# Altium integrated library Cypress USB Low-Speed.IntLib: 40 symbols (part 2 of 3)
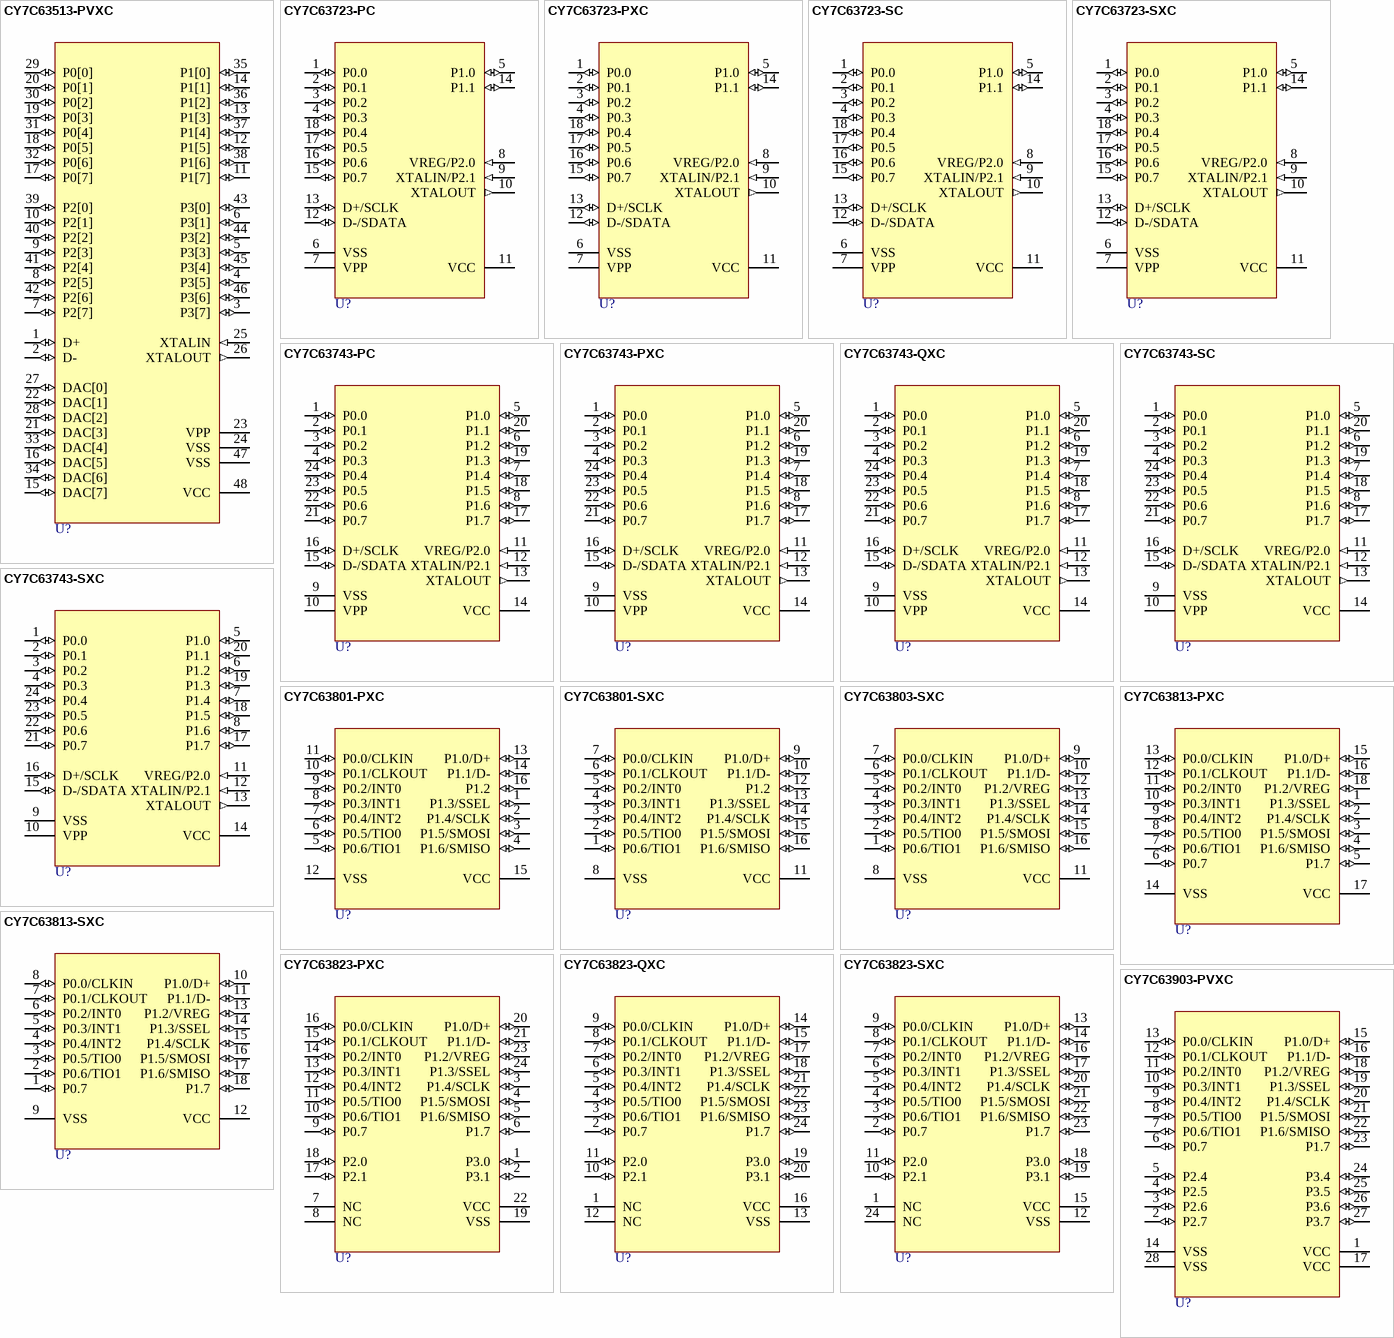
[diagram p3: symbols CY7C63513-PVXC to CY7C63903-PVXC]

## CY7C63723-PC
designator U?
enCoRe, Low-Speed Combination USB and PS/2 Peripheral Controller, 8KB EPROM, 18-Pin PDIP, Commercial Grade
footprint P3 (DIP, 18-Leads, Row Spacing 7.62mm, Pitch 2.54mm, Body 22.73x6.48mm)
pins: 1 P0.0 (io) "GPIO Port 0 capable of sinking up to 50 mA/pin, or sinking controlled low or high programmable current. Can also source 2 mA current, provide a resistive pull-up, or serve as a high-impedance input. Provides input to Capture Timer A.", 2 P0.1 (io) "GPIO Port 0 capable of sinking up to 50 mA/pin, or sinking controlled low or high programmable current. Can also source 2 mA current, provide a resistive pull-up, or serve as a high-impedance input. Provides input to Capture Timer B.", 3 P0.2 (io) "GPIO Port 0 capable of sinking up to 50 mA/pin, or sinking controlled low or high programmable current. Can also source 2 mA current, provide a resistive pull-up, or serve as a high-impedance input.", 4 P0.3 (io) "GPIO Port 0 capable of sinking up to 50 mA/pin, or sinking controlled low or high programmable current. Can also source 2 mA current, provide a resistive pull-up, or serve as a high-impedance input.", 5 P1.0 (io) "IO Port 1 capable of sinking up to 50 mA/pin, or sinking controlled low or high programmable current. Can also source 2 mA current, provide a resistive pull-up, or serve as a high-impedance input.", 6 VSS (power) "Ground", 7 VPP (power) "Programming voltage supply, ground for normal operation", 8 VREG/P2.0 (in) "Voltage supply for 1.3-kOhm USB pull-up resistor (3.3V nominal). Also serves as P2.0 input.", 9 XTALIN/P2.1 (in) "6-MHz ceramic resonator or external clock input, or P2.1 input", 10 XTALOUT (out) "6-MHz ceramic resonator return pin or internal oscillator output", 11 VCC (power) "Voltage supply", 12 D-/SDATA (io) "USB differential data line or PS/2 data signal", 13 D+/SCLK (io) "USB differential data line or PS/2 clock signal", 14 P1.1 (io) "IO Port 1 capable of sinking up to 50 mA/pin, or sinking controlled low or high programmable current. Can also source 2 mA current, provide a resistive pull-up, or serve as a high-impedance input.", 15 P0.7 (io) "GPIO Port 0 capable of sinking up to 50 mA/pin, or sinking controlled low or high programmable current. Can also source 2 mA current, provide a resistive pull-up, or serve as a high-impedance input.", 16 P0.6 (io) "GPIO Port 0 capable of sinking up to 50 mA/pin, or sinking controlled low or high programmable current. Can also source 2 mA current, provide a resistive pull-up, or serve as a high-impedance input.", 17 P0.5 (io) "GPIO Port 0 capable of sinking up to 50 mA/pin, or sinking controlled low or high programmable current. Can also source 2 mA current, provide a resistive pull-up, or serve as a high-impedance input.", 18 P0.4 (io) "GPIO Port 0 capable of sinking up to 50 mA/pin, or sinking controlled low or high programmable current. Can also source 2 mA current, provide a resistive pull-up, or serve as a high-impedance input."

## CY7C63723-PXC
designator U?
enCoRe, Low-Speed Combination USB and PS/2 Peripheral Controller, 8KB EPROM, 18-Pin PDIP, Commercial Grade, Pb-free
footprint P3 (DIP, 18-Leads, Row Spacing 7.62mm, Pitch 2.54mm, Body 22.73x6.48mm)
pins: 1 P0.0 (io) "GPIO Port 0 capable of sinking up to 50 mA/pin, or sinking controlled low or high programmable current. Can also source 2 mA current, provide a resistive pull-up, or serve as a high-impedance input. Provides input to Capture Timer A.", 2 P0.1 (io) "GPIO Port 0 capable of sinking up to 50 mA/pin, or sinking controlled low or high programmable current. Can also source 2 mA current, provide a resistive pull-up, or serve as a high-impedance input. Provides input to Capture Timer B.", 3 P0.2 (io) "GPIO Port 0 capable of sinking up to 50 mA/pin, or sinking controlled low or high programmable current. Can also source 2 mA current, provide a resistive pull-up, or serve as a high-impedance input.", 4 P0.3 (io) "GPIO Port 0 capable of sinking up to 50 mA/pin, or sinking controlled low or high programmable current. Can also source 2 mA current, provide a resistive pull-up, or serve as a high-impedance input.", 5 P1.0 (io) "IO Port 1 capable of sinking up to 50 mA/pin, or sinking controlled low or high programmable current. Can also source 2 mA current, provide a resistive pull-up, or serve as a high-impedance input.", 6 VSS (power) "Ground", 7 VPP (power) "Programming voltage supply, ground for normal operation", 8 VREG/P2.0 (in) "Voltage supply for 1.3-kOhm USB pull-up resistor (3.3V nominal). Also serves as P2.0 input.", 9 XTALIN/P2.1 (in) "6-MHz ceramic resonator or external clock input, or P2.1 input", 10 XTALOUT (out) "6-MHz ceramic resonator return pin or internal oscillator output", 11 VCC (power) "Voltage supply", 12 D-/SDATA (io) "USB differential data line or PS/2 data signal", 13 D+/SCLK (io) "USB differential data line or PS/2 clock signal", 14 P1.1 (io) "IO Port 1 capable of sinking up to 50 mA/pin, or sinking controlled low or high programmable current. Can also source 2 mA current, provide a resistive pull-up, or serve as a high-impedance input.", 15 P0.7 (io) "GPIO Port 0 capable of sinking up to 50 mA/pin, or sinking controlled low or high programmable current. Can also source 2 mA current, provide a resistive pull-up, or serve as a high-impedance input.", 16 P0.6 (io) "GPIO Port 0 capable of sinking up to 50 mA/pin, or sinking controlled low or high programmable current. Can also source 2 mA current, provide a resistive pull-up, or serve as a high-impedance input.", 17 P0.5 (io) "GPIO Port 0 capable of sinking up to 50 mA/pin, or sinking controlled low or high programmable current. Can also source 2 mA current, provide a resistive pull-up, or serve as a high-impedance input.", 18 P0.4 (io) "GPIO Port 0 capable of sinking up to 50 mA/pin, or sinking controlled low or high programmable current. Can also source 2 mA current, provide a resistive pull-up, or serve as a high-impedance input."

## CY7C63723-SC
designator U?
enCoRe, Low-Speed Combination USB and PS/2 Peripheral Controller, 8KB EPROM, 18-Pin SOIC, Commercial Grade
footprint S3_N (SOIC, 18-Leads, Body 11.6x7.5mm, Pitch 1.27mm, IPC Medium Density)
footprint S3_L (SOIC, 18-Leads, Body 11.6x7.5mm, Pitch 1.27mm, IPC High Density)
footprint S3_M (SOIC, 18-Leads, Body 11.6x7.5mm, Pitch 1.27mm, IPC Low Density)
pins: 1 P0.0 (io) "GPIO Port 0 capable of sinking up to 50 mA/pin, or sinking controlled low or high programmable current. Can also source 2 mA current, provide a resistive pull-up, or serve as a high-impedance input. Provides input to Capture Timer A.", 2 P0.1 (io) "GPIO Port 0 capable of sinking up to 50 mA/pin, or sinking controlled low or high programmable current. Can also source 2 mA current, provide a resistive pull-up, or serve as a high-impedance input. Provides input to Capture Timer B.", 3 P0.2 (io) "GPIO Port 0 capable of sinking up to 50 mA/pin, or sinking controlled low or high programmable current. Can also source 2 mA current, provide a resistive pull-up, or serve as a high-impedance input.", 4 P0.3 (io) "GPIO Port 0 capable of sinking up to 50 mA/pin, or sinking controlled low or high programmable current. Can also source 2 mA current, provide a resistive pull-up, or serve as a high-impedance input.", 5 P1.0 (io) "IO Port 1 capable of sinking up to 50 mA/pin, or sinking controlled low or high programmable current. Can also source 2 mA current, provide a resistive pull-up, or serve as a high-impedance input.", 6 VSS (power) "Ground", 7 VPP (power) "Programming voltage supply, ground for normal operation", 8 VREG/P2.0 (in) "Voltage supply for 1.3-kOhm USB pull-up resistor (3.3V nominal). Also serves as P2.0 input.", 9 XTALIN/P2.1 (in) "6-MHz ceramic resonator or external clock input, or P2.1 input", 10 XTALOUT (out) "6-MHz ceramic resonator return pin or internal oscillator output", 11 VCC (power) "Voltage supply", 12 D-/SDATA (io) "USB differential data line or PS/2 data signal", 13 D+/SCLK (io) "USB differential data line or PS/2 clock signal", 14 P1.1 (io) "IO Port 1 capable of sinking up to 50 mA/pin, or sinking controlled low or high programmable current. Can also source 2 mA current, provide a resistive pull-up, or serve as a high-impedance input.", 15 P0.7 (io) "GPIO Port 0 capable of sinking up to 50 mA/pin, or sinking controlled low or high programmable current. Can also source 2 mA current, provide a resistive pull-up, or serve as a high-impedance input.", 16 P0.6 (io) "GPIO Port 0 capable of sinking up to 50 mA/pin, or sinking controlled low or high programmable current. Can also source 2 mA current, provide a resistive pull-up, or serve as a high-impedance input.", 17 P0.5 (io) "GPIO Port 0 capable of sinking up to 50 mA/pin, or sinking controlled low or high programmable current. Can also source 2 mA current, provide a resistive pull-up, or serve as a high-impedance input.", 18 P0.4 (io) "GPIO Port 0 capable of sinking up to 50 mA/pin, or sinking controlled low or high programmable current. Can also source 2 mA current, provide a resistive pull-up, or serve as a high-impedance input."

## CY7C63723-SXC
designator U?
enCoRe, Low-Speed Combination USB and PS/2 Peripheral Controller, 8KB EPROM, 18-Pin SOIC, Commercial Grade, Pb-free
footprint S3_N (SOIC, 18-Leads, Body 11.6x7.5mm, Pitch 1.27mm, IPC Medium Density)
footprint S3_L (SOIC, 18-Leads, Body 11.6x7.5mm, Pitch 1.27mm, IPC High Density)
footprint S3_M (SOIC, 18-Leads, Body 11.6x7.5mm, Pitch 1.27mm, IPC Low Density)
pins: 1 P0.0 (io) "GPIO Port 0 capable of sinking up to 50 mA/pin, or sinking controlled low or high programmable current. Can also source 2 mA current, provide a resistive pull-up, or serve as a high-impedance input. Provides input to Capture Timer A.", 2 P0.1 (io) "GPIO Port 0 capable of sinking up to 50 mA/pin, or sinking controlled low or high programmable current. Can also source 2 mA current, provide a resistive pull-up, or serve as a high-impedance input. Provides input to Capture Timer B.", 3 P0.2 (io) "GPIO Port 0 capable of sinking up to 50 mA/pin, or sinking controlled low or high programmable current. Can also source 2 mA current, provide a resistive pull-up, or serve as a high-impedance input.", 4 P0.3 (io) "GPIO Port 0 capable of sinking up to 50 mA/pin, or sinking controlled low or high programmable current. Can also source 2 mA current, provide a resistive pull-up, or serve as a high-impedance input.", 5 P1.0 (io) "IO Port 1 capable of sinking up to 50 mA/pin, or sinking controlled low or high programmable current. Can also source 2 mA current, provide a resistive pull-up, or serve as a high-impedance input.", 6 VSS (power) "Ground", 7 VPP (power) "Programming voltage supply, ground for normal operation", 8 VREG/P2.0 (in) "Voltage supply for 1.3-kOhm USB pull-up resistor (3.3V nominal). Also serves as P2.0 input.", 9 XTALIN/P2.1 (in) "6-MHz ceramic resonator or external clock input, or P2.1 input", 10 XTALOUT (out) "6-MHz ceramic resonator return pin or internal oscillator output", 11 VCC (power) "Voltage supply", 12 D-/SDATA (io) "USB differential data line or PS/2 data signal", 13 D+/SCLK (io) "USB differential data line or PS/2 clock signal", 14 P1.1 (io) "IO Port 1 capable of sinking up to 50 mA/pin, or sinking controlled low or high programmable current. Can also source 2 mA current, provide a resistive pull-up, or serve as a high-impedance input.", 15 P0.7 (io) "GPIO Port 0 capable of sinking up to 50 mA/pin, or sinking controlled low or high programmable current. Can also source 2 mA current, provide a resistive pull-up, or serve as a high-impedance input.", 16 P0.6 (io) "GPIO Port 0 capable of sinking up to 50 mA/pin, or sinking controlled low or high programmable current. Can also source 2 mA current, provide a resistive pull-up, or serve as a high-impedance input.", 17 P0.5 (io) "GPIO Port 0 capable of sinking up to 50 mA/pin, or sinking controlled low or high programmable current. Can also source 2 mA current, provide a resistive pull-up, or serve as a high-impedance input.", 18 P0.4 (io) "GPIO Port 0 capable of sinking up to 50 mA/pin, or sinking controlled low or high programmable current. Can also source 2 mA current, provide a resistive pull-up, or serve as a high-impedance input."

## CY7C63743-PC
designator U?
enCoRe, Low-Speed Combination USB and PS/2 Peripheral Controller, 8KB EPROM, 24-Pin PDIP, Commercial Grade
footprint P13 (DIP, 24-Leads, Row Spacing 7.62mm, Pitch 2.54mm, Body 31.75x6.6mm)
pins: 1 P0.0 (io) "GPIO Port 0 capable of sinking up to 50 mA/pin, or sinking controlled low or high programmable current. Can also source 2 mA current, provide a resistive pull-up, or serve as a high-impedance input. Provides input to Capture Timer A.", 2 P0.1 (io) "GPIO Port 0 capable of sinking up to 50 mA/pin, or sinking controlled low or high programmable current. Can also source 2 mA current, provide a resistive pull-up, or serve as a high-impedance input. Provides input to Capture Timer B.", 3 P0.2 (io) "GPIO Port 0 capable of sinking up to 50 mA/pin, or sinking controlled low or high programmable current. Can also source 2 mA current, provide a resistive pull-up, or serve as a high-impedance input.", 4 P0.3 (io) "GPIO Port 0 capable of sinking up to 50 mA/pin, or sinking controlled low or high programmable current. Can also source 2 mA current, provide a resistive pull-up, or serve as a high-impedance input.", 5 P1.0 (io) "IO Port 1 capable of sinking up to 50 mA/pin, or sinking controlled low or high programmable current. Can also source 2 mA current, provide a resistive pull-up, or serve as a high-impedance input.", 6 P1.2 (io) "IO Port 1 capable of sinking up to 50 mA/pin, or sinking controlled low or high programmable current. Can also source 2 mA current, provide a resistive pull-up, or serve as a high-impedance input.", 7 P1.4 (io) "IO Port 1 capable of sinking up to 50 mA/pin, or sinking controlled low or high programmable current. Can also source 2 mA current, provide a resistive pull-up, or serve as a high-impedance input.", 8 P1.6 (io) "IO Port 1 capable of sinking up to 50 mA/pin, or sinking controlled low or high programmable current. Can also source 2 mA current, provide a resistive pull-up, or serve as a high-impedance input.", 9 VSS (power) "Ground", 10 VPP (power) "Programming voltage supply, ground for normal operation", 11 VREG/P2.0 (in) "Voltage supply for 1.3-kOhm USB pull-up resistor (3.3V nominal). Also serves as P2.0 input.", 12 XTALIN/P2.1 (in) "6-MHz ceramic resonator or external clock input, or P2.1 input", 13 XTALOUT (out) "6-MHz ceramic resonator return pin or internal oscillator output", 14 VCC (power) "Voltage supply", 15 D-/SDATA (io) "USB differential data line or PS/2 data signal", 16 D+/SCLK (io) "USB differential data line or PS/2 clock signal", 17 P1.7 (io) "IO Port 1 capable of sinking up to 50 mA/pin, or sinking controlled low or high programmable current. Can also source 2 mA current, provide a resistive pull-up, or serve as a high-impedance input.", 18 P1.5 (io) "IO Port 1 capable of sinking up to 50 mA/pin, or sinking controlled low or high programmable current. Can also source 2 mA current, provide a resistive pull-up, or serve as a high-impedance input.", 19 P1.3 (io) "IO Port 1 capable of sinking up to 50 mA/pin, or sinking controlled low or high programmable current. Can also source 2 mA current, provide a resistive pull-up, or serve as a high-impedance input.", 20 P1.1 (io) "IO Port 1 capable of sinking up to 50 mA/pin, or sinking controlled low or high programmable current. Can also source 2 mA current, provide a resistive pull-up, or serve as a high-impedance input.", 21 P0.7 (io) "GPIO Port 0 capable of sinking up to 50 mA/pin, or sinking controlled low or high programmable current. Can also source 2 mA current, provide a resistive pull-up, or serve as a high-impedance input.", 22 P0.6 (io) "GPIO Port 0 capable of sinking up to 50 mA/pin, or sinking controlled low or high programmable current. Can also source 2 mA current, provide a resistive pull-up, or serve as a high-impedance input.", 23 P0.5 (io) "GPIO Port 0 capable of sinking up to 50 mA/pin, or sinking controlled low or high programmable current. Can also source 2 mA current, provide a resistive pull-up, or serve as a high-impedance input.", 24 P0.4 (io) "GPIO Port 0 capable of sinking up to 50 mA/pin, or sinking controlled low or high programmable current. Can also source 2 mA current, provide a resistive pull-up, or serve as a high-impedance input."

## CY7C63743-PXC
designator U?
enCoRe, Low-Speed Combination USB and PS/2 Peripheral Controller, 8KB EPROM, 24-Pin PDIP, Commercial Grade, Pb-free
footprint P13 (DIP, 24-Leads, Row Spacing 7.62mm, Pitch 2.54mm, Body 31.75x6.6mm)
pins: 1 P0.0 (io) "GPIO Port 0 capable of sinking up to 50 mA/pin, or sinking controlled low or high programmable current. Can also source 2 mA current, provide a resistive pull-up, or serve as a high-impedance input. Provides input to Capture Timer A.", 2 P0.1 (io) "GPIO Port 0 capable of sinking up to 50 mA/pin, or sinking controlled low or high programmable current. Can also source 2 mA current, provide a resistive pull-up, or serve as a high-impedance input. Provides input to Capture Timer B.", 3 P0.2 (io) "GPIO Port 0 capable of sinking up to 50 mA/pin, or sinking controlled low or high programmable current. Can also source 2 mA current, provide a resistive pull-up, or serve as a high-impedance input.", 4 P0.3 (io) "GPIO Port 0 capable of sinking up to 50 mA/pin, or sinking controlled low or high programmable current. Can also source 2 mA current, provide a resistive pull-up, or serve as a high-impedance input.", 5 P1.0 (io) "IO Port 1 capable of sinking up to 50 mA/pin, or sinking controlled low or high programmable current. Can also source 2 mA current, provide a resistive pull-up, or serve as a high-impedance input.", 6 P1.2 (io) "IO Port 1 capable of sinking up to 50 mA/pin, or sinking controlled low or high programmable current. Can also source 2 mA current, provide a resistive pull-up, or serve as a high-impedance input.", 7 P1.4 (io) "IO Port 1 capable of sinking up to 50 mA/pin, or sinking controlled low or high programmable current. Can also source 2 mA current, provide a resistive pull-up, or serve as a high-impedance input.", 8 P1.6 (io) "IO Port 1 capable of sinking up to 50 mA/pin, or sinking controlled low or high programmable current. Can also source 2 mA current, provide a resistive pull-up, or serve as a high-impedance input.", 9 VSS (power) "Ground", 10 VPP (power) "Programming voltage supply, ground for normal operation", 11 VREG/P2.0 (in) "Voltage supply for 1.3-kOhm USB pull-up resistor (3.3V nominal). Also serves as P2.0 input.", 12 XTALIN/P2.1 (in) "6-MHz ceramic resonator or external clock input, or P2.1 input", 13 XTALOUT (out) "6-MHz ceramic resonator return pin or internal oscillator output", 14 VCC (power) "Voltage supply", 15 D-/SDATA (io) "USB differential data line or PS/2 data signal", 16 D+/SCLK (io) "USB differential data line or PS/2 clock signal", 17 P1.7 (io) "IO Port 1 capable of sinking up to 50 mA/pin, or sinking controlled low or high programmable current. Can also source 2 mA current, provide a resistive pull-up, or serve as a high-impedance input.", 18 P1.5 (io) "IO Port 1 capable of sinking up to 50 mA/pin, or sinking controlled low or high programmable current. Can also source 2 mA current, provide a resistive pull-up, or serve as a high-impedance input.", 19 P1.3 (io) "IO Port 1 capable of sinking up to 50 mA/pin, or sinking controlled low or high programmable current. Can also source 2 mA current, provide a resistive pull-up, or serve as a high-impedance input.", 20 P1.1 (io) "IO Port 1 capable of sinking up to 50 mA/pin, or sinking controlled low or high programmable current. Can also source 2 mA current, provide a resistive pull-up, or serve as a high-impedance input.", 21 P0.7 (io) "GPIO Port 0 capable of sinking up to 50 mA/pin, or sinking controlled low or high programmable current. Can also source 2 mA current, provide a resistive pull-up, or serve as a high-impedance input.", 22 P0.6 (io) "GPIO Port 0 capable of sinking up to 50 mA/pin, or sinking controlled low or high programmable current. Can also source 2 mA current, provide a resistive pull-up, or serve as a high-impedance input.", 23 P0.5 (io) "GPIO Port 0 capable of sinking up to 50 mA/pin, or sinking controlled low or high programmable current. Can also source 2 mA current, provide a resistive pull-up, or serve as a high-impedance input.", 24 P0.4 (io) "GPIO Port 0 capable of sinking up to 50 mA/pin, or sinking controlled low or high programmable current. Can also source 2 mA current, provide a resistive pull-up, or serve as a high-impedance input."

## CY7C63743-QXC
designator U?
enCoRe, Low-Speed Combination USB and PS/2 Peripheral Controller, 8KB EPROM, 24-Pin QSOP, Commercial Grade, Pb-free
footprint Q13_N (SOP, 24-Leads, Body 8.6x3.9mm, Pitch 0.635mm, IPC Medium Density)
footprint Q13_L (SOP, 24-Leads, Body 8.6x3.9mm, Pitch 0.635mm, IPC High Density)
footprint Q13_M (SOP, 24-Leads, Body 8.6x3.9mm, Pitch 0.635mm, IPC Low Density)
pins: 1 P0.0 (io) "GPIO Port 0 capable of sinking up to 50 mA/pin, or sinking controlled low or high programmable current. Can also source 2 mA current, provide a resistive pull-up, or serve as a high-impedance input. Provides input to Capture Timer A.", 2 P0.1 (io) "GPIO Port 0 capable of sinking up to 50 mA/pin, or sinking controlled low or high programmable current. Can also source 2 mA current, provide a resistive pull-up, or serve as a high-impedance input. Provides input to Capture Timer B.", 3 P0.2 (io) "GPIO Port 0 capable of sinking up to 50 mA/pin, or sinking controlled low or high programmable current. Can also source 2 mA current, provide a resistive pull-up, or serve as a high-impedance input.", 4 P0.3 (io) "GPIO Port 0 capable of sinking up to 50 mA/pin, or sinking controlled low or high programmable current. Can also source 2 mA current, provide a resistive pull-up, or serve as a high-impedance input.", 5 P1.0 (io) "IO Port 1 capable of sinking up to 50 mA/pin, or sinking controlled low or high programmable current. Can also source 2 mA current, provide a resistive pull-up, or serve as a high-impedance input.", 6 P1.2 (io) "IO Port 1 capable of sinking up to 50 mA/pin, or sinking controlled low or high programmable current. Can also source 2 mA current, provide a resistive pull-up, or serve as a high-impedance input.", 7 P1.4 (io) "IO Port 1 capable of sinking up to 50 mA/pin, or sinking controlled low or high programmable current. Can also source 2 mA current, provide a resistive pull-up, or serve as a high-impedance input.", 8 P1.6 (io) "IO Port 1 capable of sinking up to 50 mA/pin, or sinking controlled low or high programmable current. Can also source 2 mA current, provide a resistive pull-up, or serve as a high-impedance input.", 9 VSS (power) "Ground", 10 VPP (power) "Programming voltage supply, ground for normal operation", 11 VREG/P2.0 (in) "Voltage supply for 1.3-kOhm USB pull-up resistor (3.3V nominal). Also serves as P2.0 input.", 12 XTALIN/P2.1 (in) "6-MHz ceramic resonator or external clock input, or P2.1 input", 13 XTALOUT (out) "6-MHz ceramic resonator return pin or internal oscillator output", 14 VCC (power) "Voltage supply", 15 D-/SDATA (io) "USB differential data line or PS/2 data signal", 16 D+/SCLK (io) "USB differential data line or PS/2 clock signal", 17 P1.7 (io) "IO Port 1 capable of sinking up to 50 mA/pin, or sinking controlled low or high programmable current. Can also source 2 mA current, provide a resistive pull-up, or serve as a high-impedance input.", 18 P1.5 (io) "IO Port 1 capable of sinking up to 50 mA/pin, or sinking controlled low or high programmable current. Can also source 2 mA current, provide a resistive pull-up, or serve as a high-impedance input.", 19 P1.3 (io) "IO Port 1 capable of sinking up to 50 mA/pin, or sinking controlled low or high programmable current. Can also source 2 mA current, provide a resistive pull-up, or serve as a high-impedance input.", 20 P1.1 (io) "IO Port 1 capable of sinking up to 50 mA/pin, or sinking controlled low or high programmable current. Can also source 2 mA current, provide a resistive pull-up, or serve as a high-impedance input.", 21 P0.7 (io) "GPIO Port 0 capable of sinking up to 50 mA/pin, or sinking controlled low or high programmable current. Can also source 2 mA current, provide a resistive pull-up, or serve as a high-impedance input.", 22 P0.6 (io) "GPIO Port 0 capable of sinking up to 50 mA/pin, or sinking controlled low or high programmable current. Can also source 2 mA current, provide a resistive pull-up, or serve as a high-impedance input.", 23 P0.5 (io) "GPIO Port 0 capable of sinking up to 50 mA/pin, or sinking controlled low or high programmable current. Can also source 2 mA current, provide a resistive pull-up, or serve as a high-impedance input.", 24 P0.4 (io) "GPIO Port 0 capable of sinking up to 50 mA/pin, or sinking controlled low or high programmable current. Can also source 2 mA current, provide a resistive pull-up, or serve as a high-impedance input."

## CY7C63743-SC
designator U?
enCoRe, Low-Speed Combination USB and PS/2 Peripheral Controller, 8KB EPROM, 24-Pin SOIC,Commercial Grade
footprint S13_N (SOIC, 24-Leads, Body 15.4x7.5mm, Pitch 1.27mm, IPC Medium Density)
footprint S13_L (SOIC, 24-Leads, Body 15.4x7.5mm, Pitch 1.27mm, IPC High Density)
footprint S13_M (SOIC, 24-Leads, Body 15.4x7.5mm, Pitch 1.27mm, IPC Low Density)
pins: 1 P0.0 (io) "GPIO Port 0 capable of sinking up to 50 mA/pin, or sinking controlled low or high programmable current. Can also source 2 mA current, provide a resistive pull-up, or serve as a high-impedance input. Provides input to Capture Timer A.", 2 P0.1 (io) "GPIO Port 0 capable of sinking up to 50 mA/pin, or sinking controlled low or high programmable current. Can also source 2 mA current, provide a resistive pull-up, or serve as a high-impedance input. Provides input to Capture Timer B.", 3 P0.2 (io) "GPIO Port 0 capable of sinking up to 50 mA/pin, or sinking controlled low or high programmable current. Can also source 2 mA current, provide a resistive pull-up, or serve as a high-impedance input.", 4 P0.3 (io) "GPIO Port 0 capable of sinking up to 50 mA/pin, or sinking controlled low or high programmable current. Can also source 2 mA current, provide a resistive pull-up, or serve as a high-impedance input.", 5 P1.0 (io) "IO Port 1 capable of sinking up to 50 mA/pin, or sinking controlled low or high programmable current. Can also source 2 mA current, provide a resistive pull-up, or serve as a high-impedance input.", 6 P1.2 (io) "IO Port 1 capable of sinking up to 50 mA/pin, or sinking controlled low or high programmable current. Can also source 2 mA current, provide a resistive pull-up, or serve as a high-impedance input.", 7 P1.4 (io) "IO Port 1 capable of sinking up to 50 mA/pin, or sinking controlled low or high programmable current. Can also source 2 mA current, provide a resistive pull-up, or serve as a high-impedance input.", 8 P1.6 (io) "IO Port 1 capable of sinking up to 50 mA/pin, or sinking controlled low or high programmable current. Can also source 2 mA current, provide a resistive pull-up, or serve as a high-impedance input.", 9 VSS (power) "Ground", 10 VPP (power) "Programming voltage supply, ground for normal operation", 11 VREG/P2.0 (in) "Voltage supply for 1.3-kOhm USB pull-up resistor (3.3V nominal). Also serves as P2.0 input.", 12 XTALIN/P2.1 (in) "6-MHz ceramic resonator or external clock input, or P2.1 input", 13 XTALOUT (out) "6-MHz ceramic resonator return pin or internal oscillator output", 14 VCC (power) "Voltage supply", 15 D-/SDATA (io) "USB differential data line or PS/2 data signal", 16 D+/SCLK (io) "USB differential data line or PS/2 clock signal", 17 P1.7 (io) "IO Port 1 capable of sinking up to 50 mA/pin, or sinking controlled low or high programmable current. Can also source 2 mA current, provide a resistive pull-up, or serve as a high-impedance input.", 18 P1.5 (io) "IO Port 1 capable of sinking up to 50 mA/pin, or sinking controlled low or high programmable current. Can also source 2 mA current, provide a resistive pull-up, or serve as a high-impedance input.", 19 P1.3 (io) "IO Port 1 capable of sinking up to 50 mA/pin, or sinking controlled low or high programmable current. Can also source 2 mA current, provide a resistive pull-up, or serve as a high-impedance input.", 20 P1.1 (io) "IO Port 1 capable of sinking up to 50 mA/pin, or sinking controlled low or high programmable current. Can also source 2 mA current, provide a resistive pull-up, or serve as a high-impedance input.", 21 P0.7 (io) "GPIO Port 0 capable of sinking up to 50 mA/pin, or sinking controlled low or high programmable current. Can also source 2 mA current, provide a resistive pull-up, or serve as a high-impedance input.", 22 P0.6 (io) "GPIO Port 0 capable of sinking up to 50 mA/pin, or sinking controlled low or high programmable current. Can also source 2 mA current, provide a resistive pull-up, or serve as a high-impedance input.", 23 P0.5 (io) "GPIO Port 0 capable of sinking up to 50 mA/pin, or sinking controlled low or high programmable current. Can also source 2 mA current, provide a resistive pull-up, or serve as a high-impedance input.", 24 P0.4 (io) "GPIO Port 0 capable of sinking up to 50 mA/pin, or sinking controlled low or high programmable current. Can also source 2 mA current, provide a resistive pull-up, or serve as a high-impedance input."

## CY7C63743-SXC
designator U?
enCoRe, Low-Speed Combination USB and PS/2 Peripheral Controller, 8KB EPROM, 24-Pin SOIC,Commercial Grade, Pb-free
footprint S13_N (SOIC, 24-Leads, Body 15.4x7.5mm, Pitch 1.27mm, IPC Medium Density)
footprint S13_L (SOIC, 24-Leads, Body 15.4x7.5mm, Pitch 1.27mm, IPC High Density)
footprint S13_M (SOIC, 24-Leads, Body 15.4x7.5mm, Pitch 1.27mm, IPC Low Density)
pins: 1 P0.0 (io) "GPIO Port 0 capable of sinking up to 50 mA/pin, or sinking controlled low or high programmable current. Can also source 2 mA current, provide a resistive pull-up, or serve as a high-impedance input. Provides input to Capture Timer A.", 2 P0.1 (io) "GPIO Port 0 capable of sinking up to 50 mA/pin, or sinking controlled low or high programmable current. Can also source 2 mA current, provide a resistive pull-up, or serve as a high-impedance input. Provides input to Capture Timer B.", 3 P0.2 (io) "GPIO Port 0 capable of sinking up to 50 mA/pin, or sinking controlled low or high programmable current. Can also source 2 mA current, provide a resistive pull-up, or serve as a high-impedance input.", 4 P0.3 (io) "GPIO Port 0 capable of sinking up to 50 mA/pin, or sinking controlled low or high programmable current. Can also source 2 mA current, provide a resistive pull-up, or serve as a high-impedance input.", 5 P1.0 (io) "IO Port 1 capable of sinking up to 50 mA/pin, or sinking controlled low or high programmable current. Can also source 2 mA current, provide a resistive pull-up, or serve as a high-impedance input.", 6 P1.2 (io) "IO Port 1 capable of sinking up to 50 mA/pin, or sinking controlled low or high programmable current. Can also source 2 mA current, provide a resistive pull-up, or serve as a high-impedance input.", 7 P1.4 (io) "IO Port 1 capable of sinking up to 50 mA/pin, or sinking controlled low or high programmable current. Can also source 2 mA current, provide a resistive pull-up, or serve as a high-impedance input.", 8 P1.6 (io) "IO Port 1 capable of sinking up to 50 mA/pin, or sinking controlled low or high programmable current. Can also source 2 mA current, provide a resistive pull-up, or serve as a high-impedance input.", 9 VSS (power) "Ground", 10 VPP (power) "Programming voltage supply, ground for normal operation", 11 VREG/P2.0 (in) "Voltage supply for 1.3-kOhm USB pull-up resistor (3.3V nominal). Also serves as P2.0 input.", 12 XTALIN/P2.1 (in) "6-MHz ceramic resonator or external clock input, or P2.1 input", 13 XTALOUT (out) "6-MHz ceramic resonator return pin or internal oscillator output", 14 VCC (power) "Voltage supply", 15 D-/SDATA (io) "USB differential data line or PS/2 data signal", 16 D+/SCLK (io) "USB differential data line or PS/2 clock signal", 17 P1.7 (io) "IO Port 1 capable of sinking up to 50 mA/pin, or sinking controlled low or high programmable current. Can also source 2 mA current, provide a resistive pull-up, or serve as a high-impedance input.", 18 P1.5 (io) "IO Port 1 capable of sinking up to 50 mA/pin, or sinking controlled low or high programmable current. Can also source 2 mA current, provide a resistive pull-up, or serve as a high-impedance input.", 19 P1.3 (io) "IO Port 1 capable of sinking up to 50 mA/pin, or sinking controlled low or high programmable current. Can also source 2 mA current, provide a resistive pull-up, or serve as a high-impedance input.", 20 P1.1 (io) "IO Port 1 capable of sinking up to 50 mA/pin, or sinking controlled low or high programmable current. Can also source 2 mA current, provide a resistive pull-up, or serve as a high-impedance input.", 21 P0.7 (io) "GPIO Port 0 capable of sinking up to 50 mA/pin, or sinking controlled low or high programmable current. Can also source 2 mA current, provide a resistive pull-up, or serve as a high-impedance input.", 22 P0.6 (io) "GPIO Port 0 capable of sinking up to 50 mA/pin, or sinking controlled low or high programmable current. Can also source 2 mA current, provide a resistive pull-up, or serve as a high-impedance input.", 23 P0.5 (io) "GPIO Port 0 capable of sinking up to 50 mA/pin, or sinking controlled low or high programmable current. Can also source 2 mA current, provide a resistive pull-up, or serve as a high-impedance input.", 24 P0.4 (io) "GPIO Port 0 capable of sinking up to 50 mA/pin, or sinking controlled low or high programmable current. Can also source 2 mA current, provide a resistive pull-up, or serve as a high-impedance input."

## CY7C63801-PXC
designator U?
enCoRe II, Low-Speed USB Peripheral Controller, 4KB FLASH, 16-Pin PDIP, Commercial Grade, Pb-free
footprint P1 (DIP, 16-Leads, Row Spacing 7.62mm, Pitch 2.54mm, Body 19.18x6.35mm)
pins: 1 P1.3/SSEL (io) "GPIO Port 1 bit 3 - Configured individually. Alternate function is SSEL signal of the SPI bus TTL voltage thresholds", 2 P1.4/SCLK (io) "GPIO Port 1 bit 4 - Configured individually. Alternate function is SCLK signal of the SPI bus TTL voltage thresholds", 3 P1.5/SMOSI (io) "GPIO Port 1 bit 5 - Configured individually. Alternate function is SMOSI signal of the SPI bus TTL voltage thresholds", 4 P1.6/SMISO (io) "GPIO Port 1 bit 6 - Configured individually. Alternate function is SMISO signal of the SPI bus TTL voltage thresholds", 5 P0.6/TIO1 (io) "GPIO port 0 bit 6 - Configured individually Alternate function Timer capture inputs or Timer output TIO1", 6 P0.5/TIO0 (io) "GPIO port 0 bit 5 - Configured individually Alternate function Timer capture inputs or Timer output TIO0", 7 P0.4/INT2 (io) "GPIO port 0 bit 4 - Configured individually Optional rising edge interrupt INT2", 8 P0.3/INT1 (io) "GPIO port 0 bit 3 - Configured individually Optional rising edge interrupt INT1", 9 P0.2/INT0 (io) "GPIO port 0 bit 2 - Configured individually Optional rising edge interrupt INT0", 10 P0.1/CLKOUT (io) "GPIO Port 0 bit 1 - Configured individually. Oscillator output when configured as Clock Out.", 11 P0.0/CLKIN (io) "GPIO Port 0 bit 0 - Configured individually. Oscillator input when configured as Clock In.", 12 VSS (power) "Ground", 13 P1.0/D+ (io) "GPIO Port 1 bit 0 / USB D+", 14 P1.1/D- (io) "GPIO Port 1 bit 1 / USB D-", 15 VCC (power) "Power", 16 P1.2 (io) "GPIO Port 1 bit 2 - Configured individually."

## CY7C63801-SXC
designator U?
enCoRe II, Low-Speed USB Peripheral Controller, 4KB FLASH, 16-Pin SOIC, Commercial Grade, Pb-free
footprint S16.15_N (SOIC, 16-Leads, Body 9.9x3.9mm, Pitch 1.27mm, IPC Medium Density)
footprint S16.15_L (SOIC, 16-Leads, Body 9.9x3.9mm, Pitch 1.27mm, IPC High Density)
footprint S16.15_M (SOIC, 16-Leads, Body 9.9x3.9mm, Pitch 1.27mm, IPC Low Density)
pins: 1 P0.6/TIO1 (io) "GPIO port 0 bit 6 - Configured individually Alternate function Timer capture inputs or Timer output TIO1", 2 P0.5/TIO0 (io) "GPIO port 0 bit 5 - Configured individually Alternate function Timer capture inputs or Timer output TIO0", 3 P0.4/INT2 (io) "GPIO port 0 bit 4 - Configured individually Optional rising edge interrupt INT2", 4 P0.3/INT1 (io) "GPIO port 0 bit 3 - Configured individually Optional rising edge interrupt INT1", 5 P0.2/INT0 (io) "GPIO port 0 bit 2 - Configured individually Optional rising edge interrupt INT0", 6 P0.1/CLKOUT (io) "GPIO Port 0 bit 1 - Configured individually. Oscillator output when configured as Clock Out.", 7 P0.0/CLKIN (io) "GPIO Port 0 bit 0 - Configured individually. Oscillator input when configured as Clock In.", 8 VSS (power) "Ground", 9 P1.0/D+ (io) "GPIO Port 1 bit 0 / USB D+", 10 P1.1/D- (io) "GPIO Port 1 bit 1 / USB D-", 11 VCC (power) "Power", 12 P1.2 (io) "GPIO Port 1 bit 2 - Configured individually.", 13 P1.3/SSEL (io) "GPIO Port 1 bit 3 - Configured individually. Alternate function is SSEL signal of the SPI bus TTL voltage thresholds", 14 P1.4/SCLK (io) "GPIO Port 1 bit 4 - Configured individually. Alternate function is SCLK signal of the SPI bus TTL voltage thresholds", 15 P1.5/SMOSI (io) "GPIO Port 1 bit 5 - Configured individually. Alternate function is SMOSI signal of the SPI bus TTL voltage thresholds", 16 P1.6/SMISO (io) "GPIO Port 1 bit 6 - Configured individually. Alternate function is SMISO signal of the SPI bus TTL voltage thresholds"

## CY7C63803-SXC
designator U?
enCoRe II, Low-Speed USB Peripheral Controller, 8KB FLASH, 16-Pin SOIC, Commercial Grade, Pb-free
footprint S16.15_N (SOIC, 16-Leads, Body 9.9x3.9mm, Pitch 1.27mm, IPC Medium Density)
footprint S16.15_L (SOIC, 16-Leads, Body 9.9x3.9mm, Pitch 1.27mm, IPC High Density)
footprint S16.15_M (SOIC, 16-Leads, Body 9.9x3.9mm, Pitch 1.27mm, IPC Low Density)
pins: 1 P0.6/TIO1 (io) "GPIO port 0 bit 6 - Configured individually Alternate function Timer capture inputs or Timer output TIO1", 2 P0.5/TIO0 (io) "GPIO port 0 bit 5 - Configured individually Alternate function Timer capture inputs or Timer output TIO0", 3 P0.4/INT2 (io) "GPIO port 0 bit 4 - Configured individually Optional rising edge interrupt INT2", 4 P0.3/INT1 (io) "GPIO port 0 bit 3 - Configured individually Optional rising edge interrupt INT1", 5 P0.2/INT0 (io) "GPIO port 0 bit 2 - Configured individually Optional rising edge interrupt INT0", 6 P0.1/CLKOUT (io) "GPIO Port 0 bit 1 - Configured individually. Oscillator output when configured as Clock Out.", 7 P0.0/CLKIN (io) "GPIO Port 0 bit 0 - Configured individually. Oscillator input when configured as Clock In.", 8 VSS (power) "Ground", 9 P1.0/D+ (io) "GPIO Port 1 bit 0 / USB D+", 10 P1.1/D- (io) "GPIO Port 1 bit 1 / USB D-", 11 VCC (power) "Power", 12 P1.2/VREG (io) "GPIO Port 1 bit 2 - Configured individually. 3.3V if regulator is enabled.", 13 P1.3/SSEL (io) "GPIO Port 1 bit 3 - Configured individually. Alternate function is SSEL signal of the SPI bus TTL voltage thresholds", 14 P1.4/SCLK (io) "GPIO Port 1 bit 4 - Configured individually. Alternate function is SCLK signal of the SPI bus TTL voltage thresholds", 15 P1.5/SMOSI (io) "GPIO Port 1 bit 5 - Configured individually. Alternate function is SMOSI signal of the SPI bus TTL voltage thresholds", 16 P1.6/SMISO (io) "GPIO Port 1 bit 6 - Configured individually. Alternate function is SMISO signal of the SPI bus TTL voltage thresholds"

## CY7C63813-PXC
designator U?
enCoRe II, Low-Speed USB Peripheral Controller, 8KB FLASH, 18-Pin PDIP, Commercial Grade, Pb-free
footprint P3 (DIP, 18-Leads, Row Spacing 7.62mm, Pitch 2.54mm, Body 22.73x6.48mm)
pins: 1 P1.3/SSEL (io) "GPIO Port 1 bit 3 - Configured individually. Alternate function is SSEL signal of the SPI bus TTL voltage thresholds", 2 P1.4/SCLK (io) "GPIO Port 1 bit 4 - Configured individually. Alternate function is SCLK signal of the SPI bus TTL voltage thresholds", 3 P1.5/SMOSI (io) "GPIO Port 1 bit 5 - Configured individually. Alternate function is SMOSI signal of the SPI bus TTL voltage thresholds", 4 P1.6/SMISO (io) "GPIO Port 1 bit 6 - Configured individually. Alternate function is SMISO signal of the SPI bus TTL voltage thresholds", 5 P1.7 (io) "GPIO Port 1 bit 7 - Configured individually. TTL voltage threshold.", 6 P0.7 (io) "GPIO port 0 bit 7 - Configured individually", 7 P0.6/TIO1 (io) "GPIO port 0 bit 6 - Configured individually Alternate function Timer capture inputs or Timer output TIO1", 8 P0.5/TIO0 (io) "GPIO port 0 bit 5 - Configured individually Alternate function Timer capture inputs or Timer output TIO0", 9 P0.4/INT2 (io) "GPIO port 0 bit 4 - Configured individually Optional rising edge interrupt INT2", 10 P0.3/INT1 (io) "GPIO port 0 bit 3 - Configured individually Optional rising edge interrupt INT1", 11 P0.2/INT0 (io) "GPIO port 0 bit 2 - Configured individually Optional rising edge interrupt INT0", 12 P0.1/CLKOUT (io) "GPIO Port 0 bit 1 - Configured individually. Oscillator output when configured as Clock Out.", 13 P0.0/CLKIN (io) "GPIO Port 0 bit 0 - Configured individually. Oscillator input when configured as Clock In.", 14 VSS (power) "Ground", 15 P1.0/D+ (io) "GPIO Port 1 bit 0 / USB D+", 16 P1.1/D- (io) "GPIO Port 1 bit 1 / USB D-", 17 VCC (power) "Power", 18 P1.2/VREG (io) "GPIO Port 1 bit 2 - Configured individually. 3.3V if regulator is enabled. (The 3.3V regulator is not available in the CY7C63310 and CY7C63801.)"

## CY7C63813-SXC
designator U?
enCoRe II, Low-Speed USB Peripheral Controller, 8KB FLASH, 18-Pin SOIC, Commercial Grade, Pb-free
footprint S3_N (SOIC, 18-Leads, Body 11.6x7.5mm, Pitch 1.27mm, IPC Medium Density)
footprint S3_L (SOIC, 18-Leads, Body 11.6x7.5mm, Pitch 1.27mm, IPC High Density)
footprint S3_M (SOIC, 18-Leads, Body 11.6x7.5mm, Pitch 1.27mm, IPC Low Density)
pins: 1 P0.7 (io) "GPIO port 0 bit 7 - Configured individually", 2 P0.6/TIO1 (io) "GPIO port 0 bit 6 - Configured individually Alternate function Timer capture inputs or Timer output TIO1", 3 P0.5/TIO0 (io) "GPIO port 0 bit 5 - Configured individually Alternate function Timer capture inputs or Timer output TIO0", 4 P0.4/INT2 (io) "GPIO port 0 bit 4 - Configured individually Optional rising edge interrupt INT2", 5 P0.3/INT1 (io) "GPIO port 0 bit 3 - Configured individually Optional rising edge interrupt INT1", 6 P0.2/INT0 (io) "GPIO port 0 bit 2 - Configured individually Optional rising edge interrupt INT0", 7 P0.1/CLKOUT (io) "GPIO Port 0 bit 1 - Configured individually. Oscillator output when configured as Clock Out.", 8 P0.0/CLKIN (io) "GPIO Port 0 bit 0 - Configured individually. Oscillator input when configured as Clock In.", 9 VSS (power) "Ground", 10 P1.0/D+ (io) "GPIO Port 1 bit 0 / USB D+", 11 P1.1/D- (io) "GPIO Port 1 bit 1 / USB D-", 12 VCC (power) "Power", 13 P1.2/VREG (io) "GPIO Port 1 bit 2 - Configured individually. 3.3V if regulator is enabled.", 14 P1.3/SSEL (io) "GPIO Port 1 bit 3 - Configured individually. Alternate function is SSEL signal of the SPI bus TTL voltage thresholds", 15 P1.4/SCLK (io) "GPIO Port 1 bit 4 - Configured individually. Alternate function is SCLK signal of the SPI bus TTL voltage thresholds", 16 P1.5/SMOSI (io) "GPIO Port 1 bit 5 - Configured individually. Alternate function is SMOSI signal of the SPI bus TTL voltage thresholds", 17 P1.6/SMISO (io) "GPIO Port 1 bit 6 - Configured individually. Alternate function is SMISO signal of the SPI bus TTL voltage thresholds", 18 P1.7 (io) "GPIO Port 1 bit 7 - Configured individually. TTL voltage threshold."

## CY7C63823-PXC
designator U?
enCoRe II, Low-Speed USB Peripheral Controller, 8KB FLASH, 24-Pin PDIP, Commercial Grade, Pb-free
footprint P13 (DIP, 24-Leads, Row Spacing 7.62mm, Pitch 2.54mm, Body 31.75x6.6mm)
pins: 1 P3.0 (io) "GPIO Port 3 bit 0", 2 P3.1 (io) "GPIO Port 3 bit 1", 3 P1.4/SCLK (io) "GPIO Port 1 bit 4 - Configured individually. Alternate function is SCLK signal of the SPI bus TTL voltage thresholds", 4 P1.5/SMOSI (io) "GPIO Port 1 bit 5 - Configured individually. Alternate function is SMOSI signal of the SPI bus TTL voltage thresholds", 5 P1.6/SMISO (io) "GPIO Port 1 bit 6 - Configured individually. Alternate function is SMISO signal of the SPI bus TTL voltage thresholds", 6 P1.7 (io) "GPIO Port 1 bit 7 - Configured individually. TTL voltage threshold.", 7 NC "No connect", 8 NC "No connect", 9 P0.7 (io) "GPIO port 0 bit 7 - Configured individually", 10 P0.6/TIO1 (io) "GPIO port 0 bit 6 - Configured individually Alternate function Timer capture inputs or Timer output TIO1", 11 P0.5/TIO0 (io) "GPIO port 0 bit 5 - Configured individually Alternate function Timer capture inputs or Timer output TIO0", 12 P0.4/INT2 (io) "GPIO port 0 bit 4 - Configured individually Optional rising edge interrupt INT2", 13 P0.3/INT1 (io) "GPIO port 0 bit 3 - Configured individually Optional rising edge interrupt INT1", 14 P0.2/INT0 (io) "GPIO port 0 bit 2 - Configured individually Optional rising edge interrupt INT0", 15 P0.1/CLKOUT (io) "GPIO Port 0 bit 1 - Configured individually. Oscillator output when configured as Clock Out.", 16 P0.0/CLKIN (io) "GPIO Port 0 bit 0 - Configured individually. Oscillator input when configured as Clock In.", 17 P2.1 (io) "GPIO Port 2 bit 1", 18 P2.0 (io) "GPIO Port 2 bit 0", 19 VSS (power) "Ground", 20 P1.0/D+ (io) "GPIO Port 1 bit 0 / USB D+", 21 P1.1/D- (io) "GPIO Port 1 bit 1 / USB D-", 22 VCC (power) "Power", 23 P1.2/VREG (io) "GPIO Port 1 bit 2 - Configured individually. 3.3V if regulator is enabled.", 24 P1.3/SSEL (io) "GPIO Port 1 bit 3 - Configured individually. Alternate function is SSEL signal of the SPI bus TTL voltage thresholds"

## CY7C63823-QXC
designator U?
enCoRe II, Low-Speed USB Peripheral Controller, 8KB FLASH, 24-Pin QSOP, Commercial Grade, Pb-free
footprint O241_N (SOP, 24-Leads, Body 8.6x3.9mm, Pitch 0.635mm, IPC Medium Density)
footprint O241_L (SOP, 24-Leads, Body 8.6x3.9mm, Pitch 0.635mm, IPC High Density)
footprint O241_M (SOP, 24-Leads, Body 8.6x3.9mm, Pitch 0.635mm, IPC Low Density)
pins: 1 NC "No connect", 2 P0.7 (io) "GPIO port 0 bit 7 - Configured individually", 3 P0.6/TIO1 (io) "GPIO port 0 bit 6 - Configured individually Alternate function Timer capture inputs or Timer output TIO1", 4 P0.5/TIO0 (io) "GPIO port 0 bit 5 - Configured individually Alternate function Timer capture inputs or Timer output TIO0", 5 P0.4/INT2 (io) "GPIO port 0 bit 4 - Configured individually Optional rising edge interrupt INT2", 6 P0.3/INT1 (io) "GPIO port 0 bit 3 - Configured individually Optional rising edge interrupt INT1", 7 P0.2/INT0 (io) "GPIO port 0 bit 2 - Configured individually Optional rising edge interrupt INT0", 8 P0.1/CLKOUT (io) "GPIO Port 0 bit 1 - Configured individually. Oscillator output when configured as Clock Out.", 9 P0.0/CLKIN (io) "GPIO Port 0 bit 0 - Configured individually. Oscillator input when configured as Clock In.", 10 P2.1 (io) "GPIO Port 2 bit 1", 11 P2.0 (io) "GPIO Port 2 bit 0", 12 NC "No connect", 13 VSS (power) "Ground", 14 P1.0/D+ (io) "GPIO Port 1 bit 0 / USB D+", 15 P1.1/D- (io) "GPIO Port 1 bit 1 / USB D-", 16 VCC (power) "Power", 17 P1.2/VREG (io) "GPIO Port 1 bit 2 - Configured individually. 3.3V if regulator is enabled.", 18 P1.3/SSEL (io) "GPIO Port 1 bit 3 - Configured individually. Alternate function is SSEL signal of the SPI bus TTL voltage thresholds", 19 P3.0 (io) "GPIO Port 3 bit 0", 20 P3.1 (io) "GPIO Port 3 bit 1", 21 P1.4/SCLK (io) "GPIO Port 1 bit 4 - Configured individually. Alternate function is SCLK signal of the SPI bus TTL voltage thresholds", 22 P1.5/SMOSI (io) "GPIO Port 1 bit 5 - Configured individually. Alternate function is SMOSI signal of the SPI bus TTL voltage thresholds", 23 P1.6/SMISO (io) "GPIO Port 1 bit 6 - Configured individually. Alternate function is SMISO signal of the SPI bus TTL voltage thresholds", 24 P1.7 (io) "GPIO Port 1 bit 7 - Configured individually. TTL voltage threshold."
